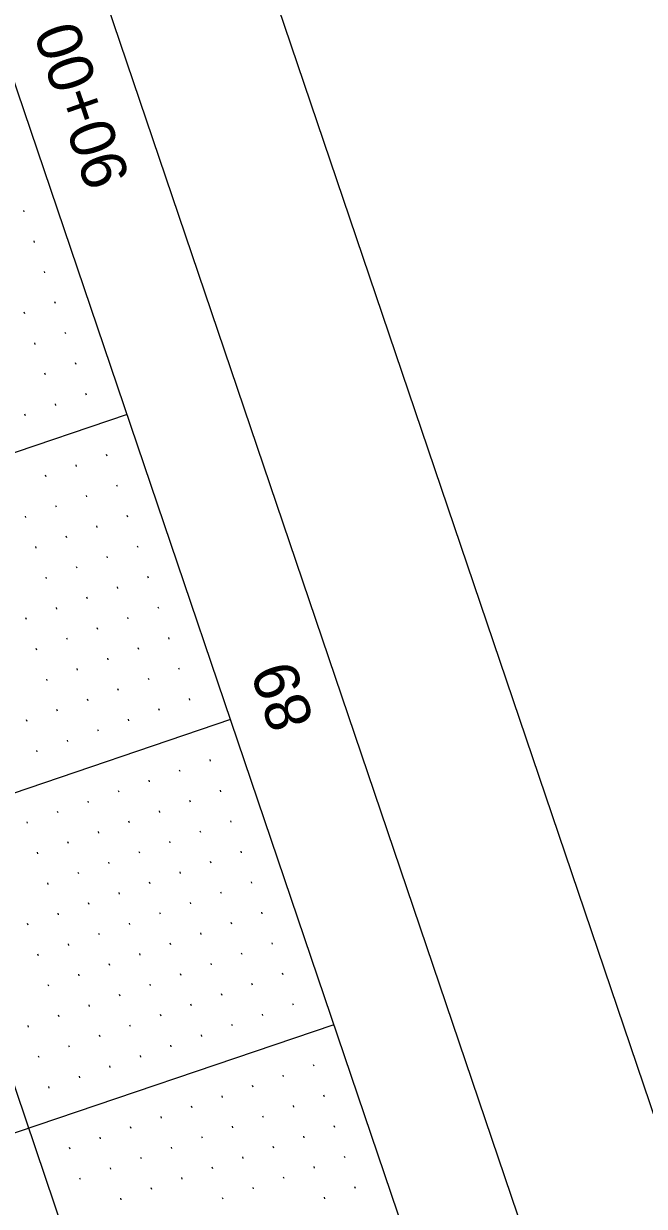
# Model space of a CAD drawing. Extents: x 2150318 to 2152065, y 143281 to 145371.
# Drawn here: x 2151803.3 to 2151899.7, y 143858.1 to 144041.7 of the extents above; entities that cross this region are included whole.
import ezdxf

# ---------------------------------------------------------------- set-up
doc = ezdxf.new("R2010")
doc.units = 0
for name, color, linetype in [('SHT_Plan_Profile_Sheet_Sta_Txt', 7, 'Continuous'), ('SHT_Plot_Shape_Half', 7, 'Continuous'), ('SHT_Profile_Grid_Major', 7, 'Continuous'), ('SHT_Profile_Grid_Minor', 7, 'Continuous'), ('SHT_Sheet_Border', 7, 'Continuous')]:
    doc.layers.add(name, color=color, linetype=linetype)

msp = doc.modelspace()

# ---------------------------------------------------------------- linework, layer by layer
at = {"layer": 'SHT_Plot_Shape_Half'}
msp.add_lwpolyline([(2150909.49, 143371.4), (2150363.35, 144981.29), (2151405.04, 145334.68), (2151951.18, 143724.79)], close=True, dxfattribs=at)
at = {"layer": 'SHT_Profile_Grid_Major'}
for p, q in [((2151832.26, 143787.41), (2151326.27, 145278.92)), ((2151819.38, 143981.03), (2151345.88, 143820.4)), ((2151835.44, 143933.68), (2151361.94, 143773.05)), ((2151851.5, 143886.33), (2151378.01, 143725.7))]:
    msp.add_line(p, q, dxfattribs=at)
at = {"layer": 'SHT_Profile_Grid_Minor'}
for p, q in [((2151803.44, 144012.45), (2151803.36, 144012.69)), ((2151805.04, 144007.72), (2151804.96, 144007.95)), ((2151806.65, 144002.98), (2151806.57, 144003.22)), ((2151808.26, 143998.25), (2151808.18, 143998.48)), ((2151803.52, 143996.64), (2151803.44, 143996.88)), ((2151805.13, 143991.9), (2151805.05, 143992.14)), ((2151809.86, 143993.51), (2151809.78, 143993.75)), ((2151811.47, 143988.78), (2151811.39, 143989.01)), ((2151806.73, 143987.17), (2151806.65, 143987.41)), ((2151813.08, 143984.04), (2151813, 143984.28)), ((2151803.61, 143980.83), (2151803.53, 143981.07)), ((2151808.34, 143982.43), (2151808.26, 143982.67)), ((2151816.29, 143974.57), (2151816.21, 143974.81)), ((2151811.55, 143972.96), (2151811.47, 143973.2)), ((2151806.82, 143971.36), (2151806.74, 143971.6)), ((2151817.89, 143969.84), (2151817.81, 143970.07)), ((2151813.16, 143968.23), (2151813.08, 143968.47)), ((2151808.42, 143966.62), (2151808.34, 143966.86)), ((2151803.69, 143965.02), (2151803.61, 143965.25)), ((2151819.5, 143965.1), (2151819.42, 143965.34)), ((2151814.77, 143963.5), (2151814.69, 143963.73)), ((2151810.03, 143961.89), (2151809.95, 143962.13)), ((2151805.3, 143960.28), (2151805.22, 143960.52)), ((2151816.37, 143958.76), (2151816.29, 143959)), ((2151821.11, 143960.37), (2151821.03, 143960.6)), ((2151811.64, 143957.15), (2151811.56, 143957.39)), ((2151806.9, 143955.55), (2151806.82, 143955.78)), ((2151822.71, 143955.63), (2151822.63, 143955.87)), ((2151817.98, 143954.03), (2151817.9, 143954.26)), ((2151813.24, 143952.42), (2151813.16, 143952.66)), ((2151808.51, 143950.81), (2151808.43, 143951.05)), ((2151824.32, 143950.9), (2151824.24, 143951.13)), ((2151803.77, 143949.21), (2151803.69, 143949.44)), ((2151819.58, 143949.29), (2151819.5, 143949.53)), ((2151810.12, 143946.08), (2151810.03, 143946.31)), ((2151814.85, 143947.68), (2151814.77, 143947.92)), ((2151825.93, 143946.16), (2151825.85, 143946.4)), ((2151805.38, 143944.47), (2151805.3, 143944.71)), ((2151821.19, 143944.56), (2151821.11, 143944.79)), ((2151816.46, 143942.95), (2151816.38, 143943.19)), ((2151811.72, 143941.34), (2151811.64, 143941.58)), ((2151827.53, 143941.43), (2151827.45, 143941.66)), ((2151806.99, 143939.74), (2151806.91, 143939.97)), ((2151822.8, 143939.82), (2151822.72, 143940.06)), ((2151818.06, 143938.21), (2151817.98, 143938.45)), ((2151808.59, 143935), (2151808.51, 143935.24)), ((2151813.33, 143936.61), (2151813.25, 143936.84)), ((2151824.4, 143935.09), (2151824.32, 143935.32)), ((2151829.14, 143936.69), (2151829.06, 143936.93)), ((2151803.86, 143933.4), (2151803.78, 143933.63)), ((2151819.67, 143933.48), (2151819.59, 143933.72)), ((2151814.93, 143931.87), (2151814.85, 143932.11)), ((2151810.2, 143930.27), (2151810.12, 143930.5)), ((2151805.46, 143928.66), (2151805.38, 143928.9)), ((2151832.35, 143927.22), (2151832.27, 143927.46)), ((2151822.88, 143924.01), (2151822.8, 143924.25)), ((2151827.62, 143925.62), (2151827.54, 143925.85)), ((2151818.15, 143922.4), (2151818.07, 143922.64)), ((2151833.96, 143922.49), (2151833.88, 143922.72)), ((2151813.41, 143920.8), (2151813.33, 143921.03)), ((2151829.22, 143920.88), (2151829.14, 143921.12)), ((2151808.68, 143919.19), (2151808.6, 143919.43)), ((2151824.49, 143919.27), (2151824.41, 143919.51)), ((2151803.94, 143917.58), (2151803.86, 143917.82)), ((2151819.75, 143917.67), (2151819.67, 143917.9)), ((2151835.56, 143917.75), (2151835.48, 143917.99)), ((2151815.02, 143916.06), (2151814.94, 143916.3)), ((2151830.83, 143916.15), (2151830.75, 143916.38)), ((2151805.55, 143912.85), (2151805.47, 143913.09)), ((2151810.28, 143914.46), (2151810.2, 143914.69)), ((2151821.36, 143912.93), (2151821.28, 143913.17)), ((2151826.09, 143914.54), (2151826.01, 143914.78)), ((2151837.17, 143913.02), (2151837.09, 143913.25)), ((2151816.62, 143911.33), (2151816.54, 143911.56)), ((2151832.44, 143911.41), (2151832.36, 143911.65)), ((2151811.89, 143909.72), (2151811.81, 143909.96)), ((2151827.7, 143909.8), (2151827.62, 143910.04)), ((2151807.15, 143908.11), (2151807.07, 143908.35)), ((2151822.97, 143908.2), (2151822.89, 143908.43)), ((2151838.78, 143908.28), (2151838.7, 143908.52)), ((2151818.23, 143906.59), (2151818.15, 143906.83)), ((2151834.04, 143906.68), (2151833.96, 143906.91)), ((2151813.5, 143904.99), (2151813.42, 143905.22)), ((2151829.31, 143905.07), (2151829.23, 143905.31)), ((2151808.76, 143903.38), (2151808.68, 143903.62)), ((2151819.84, 143901.86), (2151819.76, 143902.09)), ((2151824.57, 143903.46), (2151824.49, 143903.7)), ((2151835.65, 143901.94), (2151835.57, 143902.18)), ((2151840.38, 143903.55), (2151840.3, 143903.78)), ((2151804.03, 143901.77), (2151803.95, 143902.01)), ((2151815.1, 143900.25), (2151815.02, 143900.49)), ((2151830.91, 143900.33), (2151830.83, 143900.57)), ((2151810.37, 143898.64), (2151810.29, 143898.88)), ((2151826.18, 143898.73), (2151826.1, 143898.96)), ((2151841.99, 143898.81), (2151841.91, 143899.05)), ((2151805.63, 143897.04), (2151805.55, 143897.27)), ((2151821.44, 143897.12), (2151821.36, 143897.36)), ((2151837.25, 143897.21), (2151837.17, 143897.44)), ((2151816.71, 143895.52), (2151816.63, 143895.75)), ((2151832.52, 143895.6), (2151832.44, 143895.84)), ((2151811.97, 143893.91), (2151811.89, 143894.15)), ((2151827.78, 143893.99), (2151827.7, 143894.23)), ((2151843.6, 143894.08), (2151843.52, 143894.31)), ((2151807.24, 143892.3), (2151807.16, 143892.54)), ((2151823.05, 143892.39), (2151822.97, 143892.62)), ((2151834.13, 143890.86), (2151834.05, 143891.1)), ((2151838.86, 143892.47), (2151838.78, 143892.71)), ((2151813.58, 143889.17), (2151813.5, 143889.41)), ((2151818.31, 143890.78), (2151818.23, 143891.02)), ((2151829.39, 143889.26), (2151829.31, 143889.5)), ((2151845.2, 143889.34), (2151845.12, 143889.58)), ((2151808.84, 143887.57), (2151808.76, 143887.8)), ((2151824.66, 143887.65), (2151824.58, 143887.89)), ((2151840.47, 143887.74), (2151840.39, 143887.97)), ((2151804.11, 143885.96), (2151804.03, 143886.2)), ((2151819.92, 143886.05), (2151819.84, 143886.28)), ((2151835.73, 143886.13), (2151835.65, 143886.37)), ((2151815.19, 143884.44), (2151815.11, 143884.68)), ((2151831, 143884.52), (2151830.92, 143884.76)), ((2151810.45, 143882.83), (2151810.37, 143883.07)), ((2151826.26, 143882.92), (2151826.18, 143883.15)), ((2151805.72, 143881.23), (2151805.64, 143881.46)), ((2151821.53, 143881.31), (2151821.45, 143881.55)), ((2151848.41, 143879.87), (2151848.33, 143880.11)), ((2151812.06, 143878.1), (2151811.98, 143878.33)), ((2151816.79, 143879.7), (2151816.71, 143879.94)), ((2151843.68, 143878.27), (2151843.6, 143878.5)), ((2151807.32, 143876.49), (2151807.24, 143876.73)), ((2151838.94, 143876.66), (2151838.86, 143876.9)), ((2151834.21, 143875.05), (2151834.13, 143875.29)), ((2151850.02, 143875.14), (2151849.94, 143875.37)), ((2151829.47, 143873.45), (2151829.39, 143873.68)), ((2151845.29, 143873.53), (2151845.21, 143873.77)), ((2151824.74, 143871.84), (2151824.66, 143872.08)), ((2151840.55, 143871.92), (2151840.47, 143872.16)), ((2151820, 143870.23), (2151819.92, 143870.47)), ((2151835.82, 143870.32), (2151835.74, 143870.56)), ((2151851.63, 143870.4), (2151851.55, 143870.64)), ((2151810.54, 143867.02), (2151810.45, 143867.26)), ((2151815.27, 143868.63), (2151815.19, 143868.86)), ((2151826.35, 143867.11), (2151826.27, 143867.34)), ((2151831.08, 143868.71), (2151831, 143868.95)), ((2151842.16, 143867.19), (2151842.08, 143867.43)), ((2151846.89, 143868.8), (2151846.81, 143869.03)), ((2151821.61, 143865.5), (2151821.53, 143865.74)), ((2151837.42, 143865.58), (2151837.34, 143865.82)), ((2151853.23, 143865.67), (2151853.15, 143865.9)), ((2151816.88, 143863.89), (2151816.8, 143864.13)), ((2151832.69, 143863.98), (2151832.61, 143864.21)), ((2151848.5, 143864.06), (2151848.42, 143864.3)), ((2151812.14, 143862.29), (2151812.06, 143862.52)), ((2151827.95, 143862.37), (2151827.87, 143862.61)), ((2151843.76, 143862.45), (2151843.68, 143862.69)), ((2151823.22, 143860.76), (2151823.14, 143861)), ((2151839.03, 143860.85), (2151838.95, 143861.09)), ((2151854.84, 143860.93), (2151854.76, 143861.17)), ((2151818.48, 143859.16), (2151818.4, 143859.39)), ((2151834.29, 143859.24), (2151834.21, 143859.48)), ((2151850.1, 143859.33), (2151850.02, 143859.56))]:
    msp.add_line(p, q, dxfattribs=at)
at = {"layer": 'SHT_Sheet_Border'}
msp.add_line((2151879.61, 143803.47), (2151457.96, 145046.39), dxfattribs=at)
msp.add_lwpolyline([(2150901.85, 143471.77), (2150395.86, 144963.28), (2151390.2, 145300.6), (2151896.19, 143809.09)], close=True, dxfattribs=at)

# ---------------------------------------------------------------- texts
at = {"layer": 'SHT_Plan_Profile_Sheet_Sta_Txt'}
for s, p in [('90+00', (2151819.89, 144017.64)), ('89', (2151848.46, 143933.43))]:
    msp.add_text(s, height=7, rotation=108.7393, dxfattribs=at).set_placement(p)

doc.saveas('drawing.dxf')
